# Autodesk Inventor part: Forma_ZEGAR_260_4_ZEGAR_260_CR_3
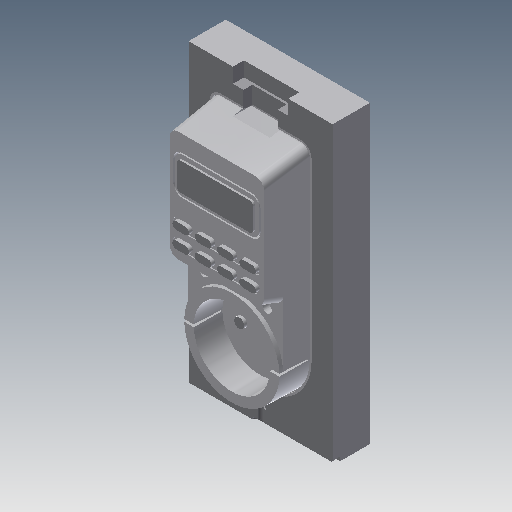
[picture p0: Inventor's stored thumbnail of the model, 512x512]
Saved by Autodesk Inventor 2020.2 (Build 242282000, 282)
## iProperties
Created: 2015-01
Part Number: Forma_ZEGAR_260_4_ZEGAR_260_CR_3
Material: Ogólny
Document SubType Name: Modeling
Designer: F.Stasiak
Density: 1 g/cm^3
Appearance: Domyślna
Catalog Web Link: www.expertbooks.pl
Manager: www.cadconsulting.pl
Company: Fabian Stasiak CAD Consulting
Author: F.Stasiak
Subject: Zbiór ćwiczeń. Autodesk Inventor 2020. Kurs Professional
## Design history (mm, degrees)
node "Forma_ZEGAR_260_4_ZEGAR_260_CR_Base"
feature "Rzeźbienie3"
feature "Bryła1::Forma_ZEGAR_260_4_ZEGAR_260_CR_Base"
tag "Bryła wyprowadzona1"
node "Bryła1"
feature "Forma_ZEGAR_260_4_ZEGAR_260_CR_Base_Bodies"
feature "Powierzchnia3"
body "Srf3"
